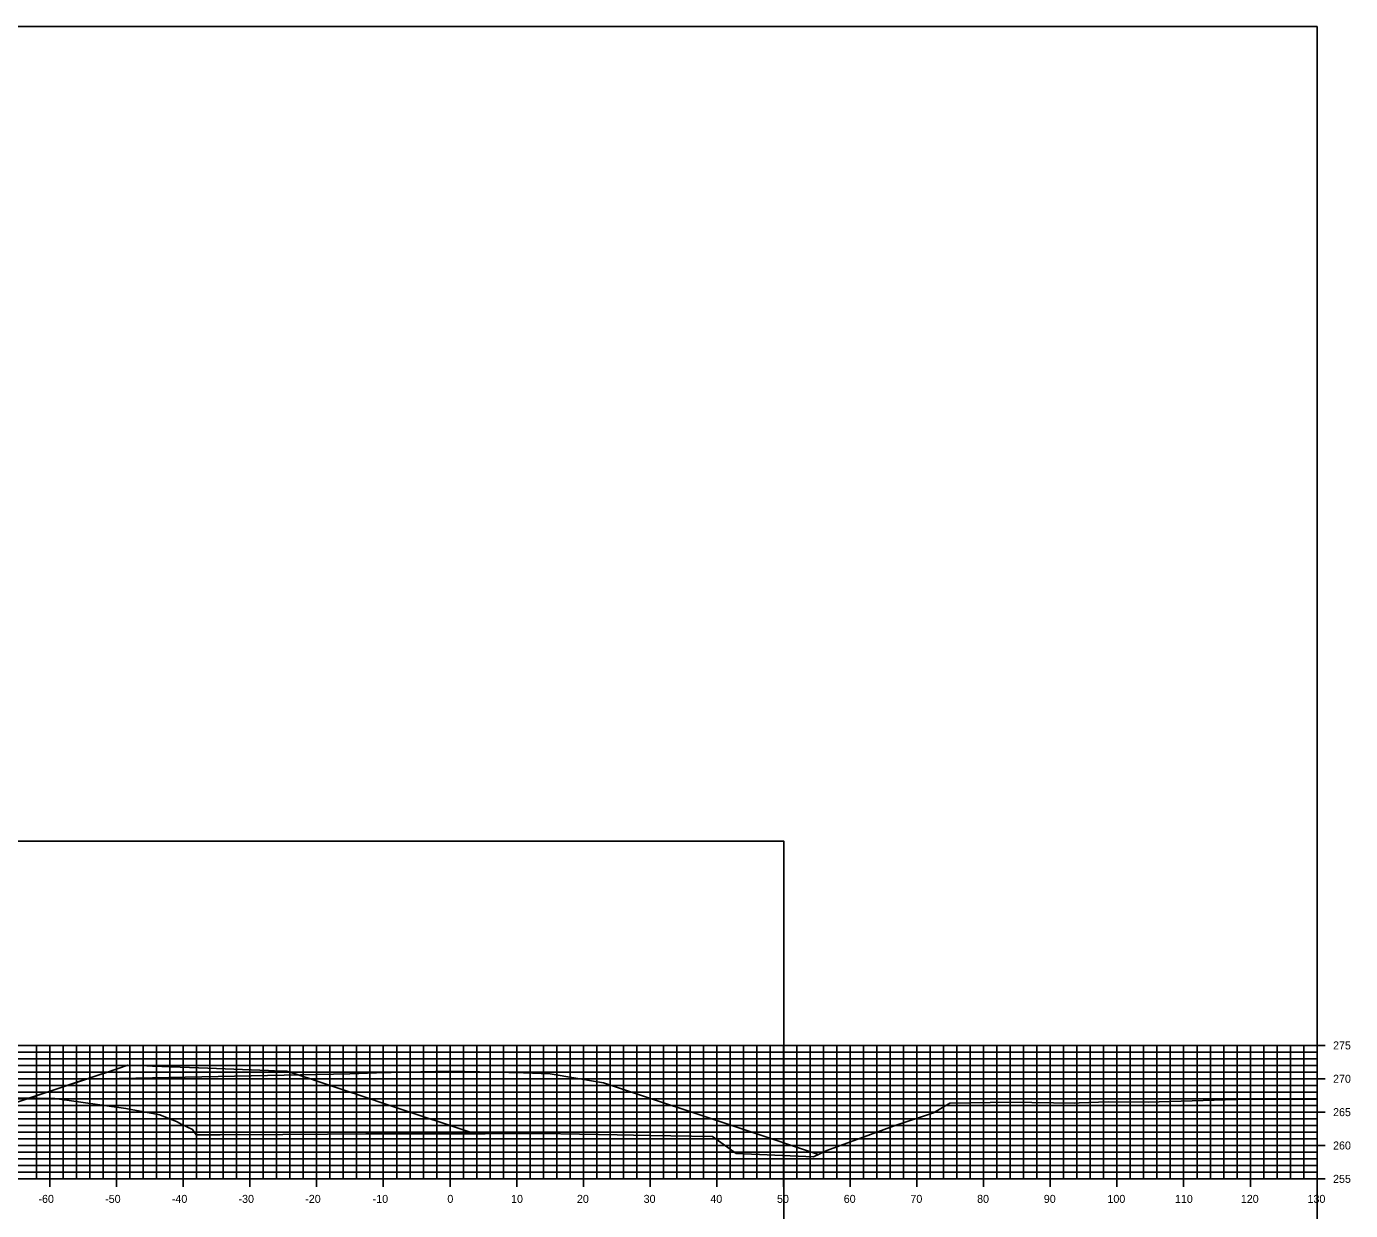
# Model space of a CAD drawing. Extents: x 1661012 to 1662122, y 670053 to 671852.
# Drawn here: x 1661923.5 to 1662122, y 671675 to 671852.4 of the extents above; entities that cross this region are included whole.
import ezdxf

# ---------------------------------------------------------------- set-up
doc = ezdxf.new("R2010")
doc.units = 0
for name, color, linetype in [('R_Concrete', 7, 'Continuous'), ('R_Concrete Hidden', 7, 'Continuous'), ('R_Erosion', 7, 'Continuous'), ('R_Exist Surface', 7, 'Continuous'), ('R_Proposed Road', 7, 'Continuous'), ('R_ROW Annot', 7, 'Continuous')]:
    doc.layers.add(name, color=color, linetype=linetype)

msp = doc.modelspace()

# ---------------------------------------------------------------- linework, layer by layer
at = {"layer": 'R_Concrete'}
for p, q in [((1661786.99, 671699.7), (1662116.99, 671699.7)), ((1661924.99, 671679.7), (1661924.99, 671699.7)), ((1661926.99, 671679.7), (1661926.99, 671699.7)), ((1661928.99, 671679.7), (1661928.99, 671699.7)), ((1661930.99, 671679.7), (1661930.99, 671699.7)), ((1661932.99, 671679.7), (1661932.99, 671699.7)), ((1661934.99, 671679.7), (1661934.99, 671699.7)), ((1661936.99, 671679.7), (1661936.99, 671699.7)), ((1661938.99, 671679.7), (1661938.99, 671699.7)), ((1661940.99, 671679.7), (1661940.99, 671699.7)), ((1661942.99, 671679.7), (1661942.99, 671699.7)), ((1661944.99, 671679.7), (1661944.99, 671699.7)), ((1661946.99, 671679.7), (1661946.99, 671699.7)), ((1661948.99, 671679.7), (1661948.99, 671699.7)), ((1661950.99, 671679.7), (1661950.99, 671699.7)), ((1661952.99, 671679.7), (1661952.99, 671699.7)), ((1661954.99, 671679.7), (1661954.99, 671699.7)), ((1661956.99, 671679.7), (1661956.99, 671699.7)), ((1661958.99, 671679.7), (1661958.99, 671699.7)), ((1661960.99, 671679.7), (1661960.99, 671699.7)), ((1661962.99, 671679.7), (1661962.99, 671699.7)), ((1661964.99, 671679.7), (1661964.99, 671699.7)), ((1661966.99, 671679.7), (1661966.99, 671699.7)), ((1661968.99, 671679.7), (1661968.99, 671699.7)), ((1661970.99, 671679.7), (1661970.99, 671699.7)), ((1661972.99, 671679.7), (1661972.99, 671699.7)), ((1661974.99, 671679.7), (1661974.99, 671699.7)), ((1661976.99, 671679.7), (1661976.99, 671699.7)), ((1661978.99, 671679.7), (1661978.99, 671699.7)), ((1661980.99, 671679.7), (1661980.99, 671699.7)), ((1661982.99, 671679.7), (1661982.99, 671699.7)), ((1661984.99, 671679.7), (1661984.99, 671699.7)), ((1661986.99, 671679.7), (1661986.99, 671699.7)), ((1661988.99, 671679.7), (1661988.99, 671699.7)), ((1661990.99, 671679.7), (1661990.99, 671699.7)), ((1661992.99, 671679.7), (1661992.99, 671699.7)), ((1661994.99, 671679.7), (1661994.99, 671699.7)), ((1661996.99, 671679.7), (1661996.99, 671699.7)), ((1661998.99, 671679.7), (1661998.99, 671699.7)), ((1662000.99, 671679.7), (1662000.99, 671699.7)), ((1662002.99, 671679.7), (1662002.99, 671699.7)), ((1662004.99, 671679.7), (1662004.99, 671699.7)), ((1662006.99, 671679.7), (1662006.99, 671699.7)), ((1662008.99, 671679.7), (1662008.99, 671699.7)), ((1662010.99, 671679.7), (1662010.99, 671699.7)), ((1662012.99, 671679.7), (1662012.99, 671699.7)), ((1662014.99, 671679.7), (1662014.99, 671699.7)), ((1662016.99, 671679.7), (1662016.99, 671699.7)), ((1662018.99, 671679.7), (1662018.99, 671699.7)), ((1662020.99, 671679.7), (1662020.99, 671699.7)), ((1662022.99, 671679.7), (1662022.99, 671699.7)), ((1662024.99, 671679.7), (1662024.99, 671699.7)), ((1662026.99, 671679.7), (1662026.99, 671699.7)), ((1662028.99, 671679.7), (1662028.99, 671699.7)), ((1662030.99, 671679.7), (1662030.99, 671699.7)), ((1662032.99, 671679.7), (1662032.99, 671699.7)), ((1662034.99, 671679.7), (1662034.99, 671699.7)), ((1662036.99, 671679.7), (1662036.99, 671699.7)), ((1662038.99, 671679.7), (1662038.99, 671699.7)), ((1662040.99, 671679.7), (1662040.99, 671699.7)), ((1662042.99, 671679.7), (1662042.99, 671699.7)), ((1662044.99, 671679.7), (1662044.99, 671699.7)), ((1662046.99, 671679.7), (1662046.99, 671699.7)), ((1662048.99, 671679.7), (1662048.99, 671699.7)), ((1662050.99, 671679.7), (1662050.99, 671699.7)), ((1662052.99, 671679.7), (1662052.99, 671699.7)), ((1662054.99, 671679.7), (1662054.99, 671699.7)), ((1662056.99, 671679.7), (1662056.99, 671699.7)), ((1662058.99, 671679.7), (1662058.99, 671699.7)), ((1662060.99, 671679.7), (1662060.99, 671699.7)), ((1662062.99, 671679.7), (1662062.99, 671699.7)), ((1662064.99, 671679.7), (1662064.99, 671699.7)), ((1662066.99, 671679.7), (1662066.99, 671699.7)), ((1662068.99, 671679.7), (1662068.99, 671699.7)), ((1662070.99, 671679.7), (1662070.99, 671699.7)), ((1662072.99, 671679.7), (1662072.99, 671699.7)), ((1662074.99, 671679.7), (1662074.99, 671699.7)), ((1662076.99, 671679.7), (1662076.99, 671699.7)), ((1662078.99, 671679.7), (1662078.99, 671699.7)), ((1662080.99, 671679.7), (1662080.99, 671699.7)), ((1662082.99, 671679.7), (1662082.99, 671699.7)), ((1662084.99, 671679.7), (1662084.99, 671699.7)), ((1662086.99, 671679.7), (1662086.99, 671699.7)), ((1662088.99, 671679.7), (1662088.99, 671699.7)), ((1662090.99, 671679.7), (1662090.99, 671699.7)), ((1662092.99, 671679.7), (1662092.99, 671699.7)), ((1662094.99, 671679.7), (1662094.99, 671699.7)), ((1662096.99, 671679.7), (1662096.99, 671699.7)), ((1662098.99, 671679.7), (1662098.99, 671699.7)), ((1662100.99, 671679.7), (1662100.99, 671699.7)), ((1662102.99, 671679.7), (1662102.99, 671699.7)), ((1662104.99, 671679.7), (1662104.99, 671699.7)), ((1662106.99, 671679.7), (1662106.99, 671699.7)), ((1662108.99, 671679.7), (1662108.99, 671699.7)), ((1662110.99, 671679.7), (1662110.99, 671699.7)), ((1662112.99, 671679.7), (1662112.99, 671699.7)), ((1662114.99, 671679.7), (1662114.99, 671699.7)), ((1662118.19, 671699.7), (1662115.79, 671699.7)), ((1662116.99, 671679.7), (1662116.99, 671699.7)), ((1661786.99, 671698.7), (1662116.99, 671698.7)), ((1661786.99, 671697.7), (1662116.99, 671697.7)), ((1662116.99, 671698.7), (1662116.39, 671698.7)), ((1662116.99, 671697.7), (1662116.39, 671697.7)), ((1661786.99, 671696.7), (1662116.99, 671696.7)), ((1661786.99, 671695.7), (1662116.99, 671695.7)), ((1662116.99, 671696.7), (1662116.39, 671696.7)), ((1662116.99, 671695.7), (1662116.39, 671695.7)), ((1661786.99, 671694.7), (1662116.99, 671694.7)), ((1661786.99, 671693.7), (1662116.99, 671693.7)), ((1662118.19, 671694.7), (1662115.79, 671694.7)), ((1662116.99, 671693.7), (1662116.39, 671693.7)), ((1661786.99, 671692.7), (1662116.99, 671692.7)), ((1661786.99, 671691.7), (1662116.99, 671691.7)), ((1662116.99, 671692.7), (1662116.39, 671692.7)), ((1662116.99, 671691.7), (1662116.39, 671691.7)), ((1661786.99, 671690.7), (1662116.99, 671690.7)), ((1661786.99, 671689.7), (1662116.99, 671689.7)), ((1662118.19, 671689.7), (1662115.79, 671689.7)), ((1662116.99, 671690.7), (1662116.39, 671690.7)), ((1661786.99, 671688.7), (1662116.99, 671688.7)), ((1661786.99, 671687.7), (1662116.99, 671687.7)), ((1662116.99, 671688.7), (1662116.39, 671688.7)), ((1662116.99, 671687.7), (1662116.39, 671687.7)), ((1661786.99, 671686.7), (1662116.99, 671686.7)), ((1661786.99, 671685.7), (1662116.99, 671685.7)), ((1662116.99, 671686.7), (1662116.39, 671686.7)), ((1662116.99, 671685.7), (1662116.39, 671685.7)), ((1661786.99, 671684.7), (1662116.99, 671684.7)), ((1661786.99, 671683.7), (1662116.99, 671683.7)), ((1662118.19, 671684.7), (1662115.79, 671684.7)), ((1662116.99, 671683.7), (1662116.39, 671683.7)), ((1661786.99, 671682.7), (1662116.99, 671682.7)), ((1661786.99, 671681.7), (1662116.99, 671681.7)), ((1662116.99, 671682.7), (1662116.39, 671682.7)), ((1662116.99, 671681.7), (1662116.39, 671681.7)), ((1661786.99, 671680.7), (1662116.99, 671680.7)), ((1661786.99, 671679.7), (1662116.99, 671679.7)), ((1661924.99, 671679.7), (1661924.99, 671680.3)), ((1661926.99, 671678.5), (1661926.99, 671680.9)), ((1661928.99, 671679.7), (1661928.99, 671680.3)), ((1661930.99, 671679.7), (1661930.99, 671680.3)), ((1661932.99, 671679.7), (1661932.99, 671680.3)), ((1661934.99, 671679.7), (1661934.99, 671680.3)), ((1661936.99, 671678.5), (1661936.99, 671680.9)), ((1661938.99, 671679.7), (1661938.99, 671680.3)), ((1661940.99, 671679.7), (1661940.99, 671680.3)), ((1661942.99, 671679.7), (1661942.99, 671680.3)), ((1661944.99, 671679.7), (1661944.99, 671680.3)), ((1661946.99, 671678.5), (1661946.99, 671680.9)), ((1661948.99, 671679.7), (1661948.99, 671680.3)), ((1661950.99, 671679.7), (1661950.99, 671680.3)), ((1661952.99, 671679.7), (1661952.99, 671680.3)), ((1661954.99, 671679.7), (1661954.99, 671680.3)), ((1661956.99, 671678.5), (1661956.99, 671680.9)), ((1661958.99, 671679.7), (1661958.99, 671680.3)), ((1661960.99, 671679.7), (1661960.99, 671680.3)), ((1661962.99, 671679.7), (1661962.99, 671680.3)), ((1661964.99, 671679.7), (1661964.99, 671680.3)), ((1661966.99, 671678.5), (1661966.99, 671680.9)), ((1661968.99, 671679.7), (1661968.99, 671680.3)), ((1661970.99, 671679.7), (1661970.99, 671680.3)), ((1661972.99, 671679.7), (1661972.99, 671680.3)), ((1661974.99, 671679.7), (1661974.99, 671680.3)), ((1661976.99, 671678.5), (1661976.99, 671680.9)), ((1661978.99, 671679.7), (1661978.99, 671680.3)), ((1661980.99, 671679.7), (1661980.99, 671680.3)), ((1661982.99, 671679.7), (1661982.99, 671680.3)), ((1661984.99, 671679.7), (1661984.99, 671680.3)), ((1661986.99, 671678.5), (1661986.99, 671680.9)), ((1661988.99, 671679.7), (1661988.99, 671680.3)), ((1661990.99, 671679.7), (1661990.99, 671680.3)), ((1661992.99, 671679.7), (1661992.99, 671680.3)), ((1661994.99, 671679.7), (1661994.99, 671680.3)), ((1661996.99, 671678.5), (1661996.99, 671680.9)), ((1661998.99, 671679.7), (1661998.99, 671680.3)), ((1662000.99, 671679.7), (1662000.99, 671680.3)), ((1662002.99, 671679.7), (1662002.99, 671680.3)), ((1662004.99, 671679.7), (1662004.99, 671680.3)), ((1662006.99, 671678.5), (1662006.99, 671680.9)), ((1662008.99, 671679.7), (1662008.99, 671680.3)), ((1662010.99, 671679.7), (1662010.99, 671680.3)), ((1662012.99, 671679.7), (1662012.99, 671680.3)), ((1662014.99, 671679.7), (1662014.99, 671680.3)), ((1662016.99, 671678.5), (1662016.99, 671680.9)), ((1662018.99, 671679.7), (1662018.99, 671680.3)), ((1662020.99, 671679.7), (1662020.99, 671680.3)), ((1662022.99, 671679.7), (1662022.99, 671680.3)), ((1662024.99, 671679.7), (1662024.99, 671680.3)), ((1662026.99, 671678.5), (1662026.99, 671680.9)), ((1662028.99, 671679.7), (1662028.99, 671680.3)), ((1662030.99, 671679.7), (1662030.99, 671680.3)), ((1662032.99, 671679.7), (1662032.99, 671680.3)), ((1662034.99, 671679.7), (1662034.99, 671680.3)), ((1662036.99, 671678.5), (1662036.99, 671680.9)), ((1662038.99, 671679.7), (1662038.99, 671680.3)), ((1662040.99, 671679.7), (1662040.99, 671680.3)), ((1662042.99, 671679.7), (1662042.99, 671680.3)), ((1662044.99, 671679.7), (1662044.99, 671680.3)), ((1662046.99, 671678.5), (1662046.99, 671680.9)), ((1662048.99, 671679.7), (1662048.99, 671680.3)), ((1662050.99, 671679.7), (1662050.99, 671680.3)), ((1662052.99, 671679.7), (1662052.99, 671680.3)), ((1662054.99, 671679.7), (1662054.99, 671680.3)), ((1662056.99, 671678.5), (1662056.99, 671680.9)), ((1662058.99, 671679.7), (1662058.99, 671680.3)), ((1662060.99, 671679.7), (1662060.99, 671680.3)), ((1662062.99, 671679.7), (1662062.99, 671680.3)), ((1662064.99, 671679.7), (1662064.99, 671680.3)), ((1662066.99, 671678.5), (1662066.99, 671680.9)), ((1662068.99, 671679.7), (1662068.99, 671680.3)), ((1662070.99, 671679.7), (1662070.99, 671680.3)), ((1662072.99, 671679.7), (1662072.99, 671680.3)), ((1662074.99, 671679.7), (1662074.99, 671680.3)), ((1662076.99, 671678.5), (1662076.99, 671680.9)), ((1662078.99, 671679.7), (1662078.99, 671680.3)), ((1662080.99, 671679.7), (1662080.99, 671680.3)), ((1662082.99, 671679.7), (1662082.99, 671680.3)), ((1662084.99, 671679.7), (1662084.99, 671680.3)), ((1662086.99, 671678.5), (1662086.99, 671680.9)), ((1662088.99, 671679.7), (1662088.99, 671680.3)), ((1662090.99, 671679.7), (1662090.99, 671680.3)), ((1662092.99, 671679.7), (1662092.99, 671680.3)), ((1662094.99, 671679.7), (1662094.99, 671680.3)), ((1662096.99, 671678.5), (1662096.99, 671680.9)), ((1662098.99, 671679.7), (1662098.99, 671680.3)), ((1662100.99, 671679.7), (1662100.99, 671680.3)), ((1662102.99, 671679.7), (1662102.99, 671680.3)), ((1662104.99, 671679.7), (1662104.99, 671680.3)), ((1662106.99, 671678.5), (1662106.99, 671680.9)), ((1662108.99, 671679.7), (1662108.99, 671680.3)), ((1662110.99, 671679.7), (1662110.99, 671680.3)), ((1662112.99, 671679.7), (1662112.99, 671680.3)), ((1662114.99, 671679.7), (1662114.99, 671680.3)), ((1662118.19, 671679.7), (1662115.79, 671679.7)), ((1662116.99, 671680.7), (1662116.39, 671680.7)), ((1662116.99, 671678.5), (1662116.99, 671680.9))]:
    msp.add_line(p, q, dxfattribs=at)
at = {"layer": 'R_Erosion'}
msp.add_lwpolyline([(1661916.6, 671691.92), (1661927.74, 671691.76), (1661938.36, 671690.27), (1661943.49, 671689.29), (1661946.07, 671688.27), (1661946.68, 671687.89), (1661948.38, 671687.08), (1661948.94, 671686.3), (1661952.55, 671686.31), (1661961.91, 671686.35), (1661968.64, 671686.42), (1661974.38, 671686.45), (1661986.4, 671686.45), (1661987.48, 671686.44), (1661992.24, 671686.46), (1662000.74, 671686.51), (1662012.05, 671686.32), (1662016.94, 671686.21), (1662026.34, 671686.04), (1662029.87, 671683.49), (1662041.48, 671683.02), (1662043.5, 671683.95), (1662053.6, 671687.67), (1662059.5, 671689.62), (1662061.93, 671691.06), (1662061.93, 671691.06), (1662071.04, 671691.22), (1662080.65, 671691.06), (1662081.31, 671691.08), (1662085.67, 671691.24), (1662091.67, 671691.22), (1662106.51, 671691.64), (1662109.07, 671691.63), (1662113.45, 671691.64), (1662116.99, 671691.65)], dxfattribs=at)
at = {"layer": 'R_Exist Surface'}
for p, q in [((1662116.99, 671679.7), (1662116.99, 671699.7)), ((1661786.99, 671679.7), (1662116.99, 671679.7))]:
    msp.add_line(p, q, dxfattribs=at)
at = {"layer": 'R_Proposed Road'}
for points in [[(1661756.99, 671659.7), (1662116.99, 671659.7), (1662116.99, 671852.4), (1661756.99, 671852.4)], [(1661677.02, 671537.62), (1662037.02, 671537.62), (1662037.02, 671730.32), (1661677.02, 671730.32)]]:
    msp.add_lwpolyline(points, close=True, dxfattribs=at)
at = {"layer": 'R_ROW Annot'}
for points in [[(1661887.61, 671691.99), (1661894.14, 671689.81), (1661906.05, 671685.85), (1661912.74, 671688.08), (1661928.67, 671693.39), (1661930, 671693.83), (1661934.7, 671695.39), (1661935.49, 671695.66), (1661938.67, 671696.72), (1661939.04, 671696.71), (1661940.67, 671696.68), (1661942.4, 671696.61), (1661950.67, 671696.29), (1661959.78, 671695.93), (1661960.67, 671695.89), (1661962.52, 671695.82), (1661962.67, 671695.81), (1661966.39, 671694.57), (1661966.63, 671694.49), (1661972.49, 671692.54), (1661972.67, 671692.48), (1661973.2, 671692.31), (1661978.44, 671690.56), (1661990.76, 671686.45)], [(1661923.98, 671691.82), (1661932.49, 671694.66), (1661964.58, 671695.3), (1661971.99, 671695.45), (1661975.99, 671695.61), (1661986.99, 671695.83), (1661997.99, 671695.61), (1662001.99, 671695.45), (1662009.4, 671694.21), (1662009.99, 671694.11), (1662031.21, 671687.05), (1662042.23, 671683.37)]]:
    msp.add_lwpolyline(points, dxfattribs=at)

# ---------------------------------------------------------------- texts
at = {"layer": 'R_Concrete Hidden'}
for s, p in [('275', (1662119.39, 671699.1)), ('270', (1662119.39, 671694.1)), ('265', (1662119.39, 671689.1)), ('260', (1662119.39, 671684.1)), ('255', (1662119.39, 671679.1)), ('-60', (1661925.28, 671676.1)), ('-50', (1661935.28, 671676.1)), ('-40', (1661945.28, 671676.1)), ('-30', (1661955.28, 671676.1)), ('-20', (1661965.28, 671676.1)), ('-10', (1661975.39, 671676.1)), ('0', (1661986.59, 671676.1)), ('10', (1661996.14, 671676.1)), ('20', (1662006.02, 671676.1)), ('30', (1662016.02, 671676.1)), ('40', (1662026.02, 671676.1)), ('50', (1662036.02, 671676.1)), ('60', (1662046.02, 671676.1)), ('70', (1662056.02, 671676.1)), ('80', (1662066.02, 671676.1)), ('90', (1662076.02, 671676.1)), ('100', (1662085.56, 671676.1)), ('110', (1662095.68, 671676.1)), ('120', (1662105.56, 671676.1)), ('130', (1662115.56, 671676.1))]:
    msp.add_text(s, height=1.2, dxfattribs=at).set_placement(p)

doc.saveas('drawing.dxf')
